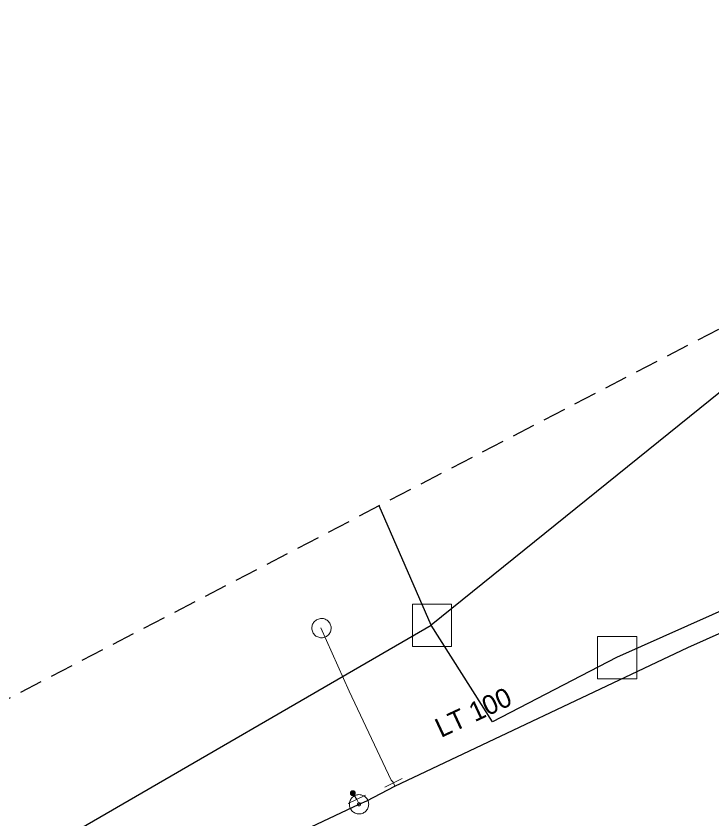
# Model space of a CAD drawing. Extents: x -688693 to -688474, y -974081 to -973994.
# Drawn here: x -688620.11 to -688584.02, y -974035.86 to -973994.23 of the extents above; entities that cross this region are included whole.
import ezdxf

# ---------------------------------------------------------------- set-up
doc = ezdxf.new("R2010")
doc.units = 0
doc.header["$LTSCALE"] = 0.4
doc.linetypes.add('MEDIUM_DASHED', pattern=[4.5, 3, -1.5])
for name, color, linetype, lineweight in [('1', 7, 'MEDIUM_DASHED', 25), ('13', 7, 'Continuous', 13), ('14', 7, 'Continuous', 25), ('17', 7, 'Continuous', 25), ('22', 7, 'Continuous', 13), ('23', 7, 'Continuous', 13), ('34', 7, 'Continuous', 13), ('47', 7, 'Continuous', 13), ('9', 7, 'Continuous', 13)]:
    doc.layers.add(name, color=color, linetype=linetype, lineweight=lineweight)

msp = doc.modelspace()

# ---------------------------------------------------------------- linework, layer by layer
at = {"layer": '1'}
msp.add_lwpolyline([(-688692.931, -974052.713), (-688674.241, -974042.463), (-688662.987, -974051.708), (-688552.455, -973994.231), (-688543.813, -974004.28), (-688496.988, -974010.309), (-688488.949, -974009.103), (-688474.077, -974014.529), (-688476.69, -974033.621), (-688494.978, -974032.616), (-688541.804, -974022.367), (-688555.67, -974019.352), (-688572.552, -974027.19), (-688578.982, -974032.415), (-688581.193, -974043.669), (-688636.057, -974069.393), (-688655.149, -974067.182), (-688651.532, -974076.829), (-688666.202, -974081.049), (-688669.82, -974071.805), (-688685.294, -974080.647), (-688689.113, -974064.369), (-688682.883, -974060.751)], close=True, dxfattribs=at)
at = {"layer": '13'}
msp.add_lwpolyline([(-688600.541, -974033.989), (-688600.574, -974033.938), (-688600.659, -974033.84), (-688602.827, -974029.23), (-688604.3, -974025.953)], dxfattribs=at)
at = {"layer": '14'}
for p, q in [((-688577.23, -974008.592), (-688598.575, -974025.813)), ((-688598.575, -974025.813), (-688601.283, -974019.622)), ((-688658.556, -974060.52), (-688598.575, -974025.813))]:
    msp.add_line(p, q, dxfattribs=at)
at = {"layer": '14', "lineweight": 13}
msp.add_line((-688600.46, -974034.151), (-688600.541, -974033.989), dxfattribs=at)
at = {"layer": '14'}
for points in [[(-688544.118, -974012.713), (-688553.402, -974013.335), (-688562.069, -974015.498), (-688588.977, -974027.483)], [(-688588.977, -974027.483), (-688595.407, -974030.817), (-688598.575, -974025.813)]]:
    msp.add_lwpolyline(points, dxfattribs=at)
at = {"layer": '14', "lineweight": 13}
msp.add_lwpolyline([(-688602.322, -974035.098), (-688602.44, -974034.846), (-688602.642, -974034.52)], dxfattribs=at)
at = {"layer": '17'}
for points in [[(-688602.322, -974035.098), (-688601.921, -974034.916), (-688600.46, -974034.151), (-688585.27, -974026.962), (-688583.34, -974026.112), (-688583.05, -974025.995)], [(-688652.752, -974058.945), (-688651.228, -974058.19), (-688641.695, -974053.653), (-688634.831, -974050.489), (-688629.499, -974047.91), (-688602.322, -974035.098)]]:
    msp.add_lwpolyline(points, dxfattribs=at)
at = {"layer": '22'}
for points in [[(-688599.554, -974024.723), (-688597.522, -974024.723), (-688597.522, -974026.916), (-688599.554, -974026.916)], [(-688589.956, -974026.393), (-688587.924, -974026.393), (-688587.924, -974028.586), (-688589.956, -974028.586)]]:
    msp.add_lwpolyline(points, close=True, dxfattribs=at)
at = {"layer": '23'}
for points in [[(-688603.779, -974026.06), (-688603.771, -974026.01), (-688603.77, -974025.957), (-688603.772, -974025.905), (-688603.782, -974025.853), (-688603.797, -974025.803), (-688603.816, -974025.755), (-688603.841, -974025.709), (-688603.869, -974025.665), (-688603.903, -974025.624), (-688603.941, -974025.588), (-688603.982, -974025.555), (-688604.025, -974025.528), (-688604.073, -974025.505), (-688604.122, -974025.486), (-688604.172, -974025.474), (-688604.225, -974025.466), (-688604.277, -974025.464), (-688604.329, -974025.468), (-688604.381, -974025.478), (-688604.431, -974025.492), (-688604.479, -974025.51), (-688604.526, -974025.535), (-688604.57, -974025.564), (-688604.609, -974025.598), (-688604.645, -974025.636), (-688604.678, -974025.676), (-688604.705, -974025.722), (-688604.728, -974025.768), (-688604.746, -974025.817), (-688604.759, -974025.868), (-688604.767, -974025.919), (-688604.769, -974025.972), (-688604.765, -974026.025), (-688604.757, -974026.076), (-688604.742, -974026.125), (-688604.723, -974026.174), (-688604.698, -974026.222), (-688604.67, -974026.264), (-688604.635, -974026.305)], [(-688604.479, -974025.51), (-688604.526, -974025.535), (-688604.57, -974025.564), (-688604.609, -974025.598), (-688604.645, -974025.636), (-688604.678, -974025.676), (-688604.705, -974025.722), (-688604.728, -974025.768), (-688604.746, -974025.817), (-688604.759, -974025.868), (-688604.767, -974025.919), (-688604.769, -974025.972), (-688604.765, -974026.025), (-688604.757, -974026.076), (-688604.742, -974026.125), (-688604.723, -974026.174), (-688604.698, -974026.222), (-688604.67, -974026.264), (-688604.635, -974026.305), (-688604.599, -974026.341), (-688604.558, -974026.374), (-688604.512, -974026.401), (-688604.465, -974026.424), (-688604.415, -974026.442), (-688604.365, -974026.456), (-688604.314, -974026.462), (-688604.261, -974026.464), (-688604.21, -974026.46), (-688604.158, -974026.451), (-688604.108, -974026.436), (-688604.059, -974026.418), (-688604.013, -974026.394), (-688603.969, -974026.364), (-688603.928, -974026.33), (-688603.892, -974026.293), (-688603.862, -974026.252), (-688603.833, -974026.208), (-688603.809, -974026.161), (-688603.791, -974026.111), (-688603.779, -974026.06)], [(-688604.635, -974026.305), (-688604.599, -974026.341), (-688604.558, -974026.374), (-688604.512, -974026.401), (-688604.465, -974026.424), (-688604.415, -974026.442), (-688604.365, -974026.456), (-688604.314, -974026.462), (-688604.261, -974026.464), (-688604.21, -974026.46), (-688604.158, -974026.451), (-688604.108, -974026.436), (-688604.059, -974026.418), (-688604.013, -974026.394), (-688603.969, -974026.364), (-688603.928, -974026.33), (-688603.892, -974026.293), (-688603.862, -974026.252), (-688603.833, -974026.208), (-688603.809, -974026.161), (-688603.791, -974026.111), (-688603.779, -974026.06), (-688603.771, -974026.01), (-688603.77, -974025.957), (-688603.772, -974025.905), (-688603.782, -974025.853), (-688603.797, -974025.803), (-688603.816, -974025.755), (-688603.841, -974025.709), (-688603.869, -974025.665), (-688603.903, -974025.624), (-688603.941, -974025.588), (-688603.982, -974025.555), (-688604.025, -974025.528), (-688604.073, -974025.505), (-688604.122, -974025.486), (-688604.172, -974025.474), (-688604.225, -974025.466), (-688604.277, -974025.464), (-688604.329, -974025.468)], [(-688604.329, -974025.468), (-688604.381, -974025.478), (-688604.431, -974025.492), (-688604.479, -974025.51)]]:
    msp.add_lwpolyline(points, dxfattribs=at)
at = {"layer": '34'}
for p, q in [((-688600.989, -974034.209), (-688600.091, -974033.769)), ((-688602.891, -974035.061), (-688601.988, -974034.631))]:
    msp.add_line(p, q, dxfattribs=at)
at = {"layer": '47'}
for points in [[(-688601.866, -974034.891), (-688601.89, -974034.845), (-688601.919, -974034.801), (-688601.952, -974034.761), (-688601.989, -974034.724), (-688602.03, -974034.691), (-688602.075, -974034.663), (-688602.121, -974034.64), (-688602.17, -974034.622), (-688602.22, -974034.608), (-688602.272, -974034.6), (-688602.325, -974034.597), (-688602.377, -974034.601), (-688602.428, -974034.609), (-688602.479, -974034.623), (-688602.528, -974034.642), (-688602.574, -974034.666), (-688602.618, -974034.695), (-688602.659, -974034.729), (-688602.695, -974034.765), (-688602.728, -974034.806), (-688602.756, -974034.851), (-688602.78, -974034.898), (-688602.798, -974034.947), (-688602.812, -974034.997), (-688602.819, -974035.048), (-688602.822, -974035.101), (-688602.819, -974035.154), (-688602.81, -974035.204), (-688602.796, -974035.255), (-688602.777, -974035.304), (-688602.753, -974035.35), (-688602.724, -974035.394), (-688602.691, -974035.435), (-688602.654, -974035.471), (-688602.613, -974035.504), (-688602.569, -974035.532), (-688602.522, -974035.556), (-688602.473, -974035.575), (-688602.422, -974035.588), (-688602.371, -974035.595), (-688602.318, -974035.598), (-688602.266, -974035.595), (-688602.215, -974035.586), (-688602.164, -974035.572), (-688602.115, -974035.553), (-688602.069, -974035.529), (-688602.025, -974035.5), (-688601.985, -974035.468), (-688601.948, -974035.43), (-688601.915, -974035.389), (-688601.887, -974035.345), (-688601.864, -974035.299), (-688601.845, -974035.25), (-688601.832, -974035.199), (-688601.824, -974035.147), (-688601.821, -974035.094), (-688601.825, -974035.043), (-688601.833, -974034.991), (-688601.847, -974034.94)], [(-688602.247, -974035.064), (-688602.251, -974035.055), (-688602.256, -974035.049), (-688602.261, -974035.043), (-688602.267, -974035.037), (-688602.274, -974035.031), (-688602.281, -974035.027), (-688602.289, -974035.022), (-688602.297, -974035.019), (-688602.305, -974035.018), (-688602.313, -974035.016), (-688602.322, -974035.016), (-688602.331, -974035.016), (-688602.339, -974035.018), (-688602.347, -974035.019), (-688602.355, -974035.023), (-688602.364, -974035.027), (-688602.37, -974035.032), (-688602.376, -974035.037), (-688602.382, -974035.043), (-688602.388, -974035.05), (-688602.392, -974035.057), (-688602.397, -974035.065), (-688602.4, -974035.073), (-688602.402, -974035.081), (-688602.403, -974035.089), (-688602.403, -974035.098), (-688602.403, -974035.107), (-688602.401, -974035.115), (-688602.4, -974035.123), (-688602.396, -974035.131), (-688602.392, -974035.14), (-688602.387, -974035.146), (-688602.382, -974035.152), (-688602.376, -974035.158), (-688602.369, -974035.164), (-688602.363, -974035.169), (-688602.354, -974035.173), (-688602.346, -974035.176), (-688602.338, -974035.178), (-688602.33, -974035.179), (-688602.321, -974035.179), (-688602.312, -974035.179), (-688602.304, -974035.177), (-688602.296, -974035.176), (-688602.288, -974035.172), (-688602.279, -974035.168), (-688602.273, -974035.163), (-688602.267, -974035.158), (-688602.261, -974035.152), (-688602.255, -974035.145), (-688602.25, -974035.139), (-688602.246, -974035.13), (-688602.243, -974035.122), (-688602.242, -974035.114), (-688602.24, -974035.106), (-688602.24, -974035.097), (-688602.24, -974035.088), (-688602.242, -974035.08), (-688602.243, -974035.072)]]:
    msp.add_lwpolyline(points, close=True, dxfattribs=at)
at = {"layer": '9'}
for points in [[(-688602.768, -974034.52), (-688602.768, -974034.533), (-688602.766, -974034.546), (-688602.763, -974034.559), (-688602.758, -974034.571), (-688602.752, -974034.583), (-688602.745, -974034.594), (-688602.737, -974034.604), (-688602.727, -974034.614), (-688602.717, -974034.622), (-688602.706, -974034.629), (-688602.694, -974034.635), (-688602.682, -974034.64), (-688602.669, -974034.643), (-688602.656, -974034.645), (-688602.643, -974034.647), (-688602.63, -974034.646), (-688602.617, -974034.644), (-688602.604, -974034.641), (-688602.592, -974034.636), (-688602.58, -974034.63), (-688602.569, -974034.623), (-688602.559, -974034.615), (-688602.549, -974034.605), (-688602.541, -974034.595), (-688602.534, -974034.584), (-688602.528, -974034.572), (-688602.523, -974034.56), (-688602.52, -974034.547), (-688602.518, -974034.534), (-688602.516, -974034.521), (-688602.517, -974034.508), (-688602.519, -974034.495), (-688602.522, -974034.482), (-688602.527, -974034.47), (-688602.532, -974034.458), (-688602.54, -974034.447), (-688602.548, -974034.437), (-688602.558, -974034.427), (-688602.568, -974034.419), (-688602.579, -974034.412), (-688602.591, -974034.406), (-688602.603, -974034.401), (-688602.616, -974034.398), (-688602.629, -974034.396), (-688602.642, -974034.395), (-688602.655, -974034.395), (-688602.668, -974034.397), (-688602.681, -974034.4), (-688602.693, -974034.405), (-688602.705, -974034.411), (-688602.716, -974034.418), (-688602.726, -974034.426), (-688602.736, -974034.436), (-688602.744, -974034.446), (-688602.751, -974034.457), (-688602.757, -974034.469), (-688602.762, -974034.481), (-688602.765, -974034.494), (-688602.767, -974034.507)], [(-688602.748, -974034.52), (-688602.749, -974034.531), (-688602.747, -974034.542), (-688602.744, -974034.553), (-688602.74, -974034.563), (-688602.735, -974034.573), (-688602.729, -974034.582), (-688602.722, -974034.591), (-688602.714, -974034.599), (-688602.705, -974034.606), (-688602.696, -974034.612), (-688602.686, -974034.617), (-688602.676, -974034.621), (-688602.665, -974034.624), (-688602.654, -974034.627), (-688602.643, -974034.627), (-688602.632, -974034.627), (-688602.621, -974034.625), (-688602.61, -974034.622), (-688602.6, -974034.618), (-688602.59, -974034.613), (-688602.581, -974034.607), (-688602.572, -974034.6), (-688602.564, -974034.592), (-688602.557, -974034.583), (-688602.551, -974034.574), (-688602.546, -974034.564), (-688602.542, -974034.554), (-688602.539, -974034.543), (-688602.537, -974034.532), (-688602.536, -974034.521), (-688602.536, -974034.51), (-688602.538, -974034.499), (-688602.541, -974034.488), (-688602.545, -974034.478), (-688602.55, -974034.468), (-688602.556, -974034.459), (-688602.563, -974034.45), (-688602.571, -974034.442), (-688602.58, -974034.435), (-688602.589, -974034.429), (-688602.599, -974034.424), (-688602.608, -974034.42), (-688602.62, -974034.417), (-688602.63, -974034.415), (-688602.642, -974034.415), (-688602.653, -974034.414), (-688602.664, -974034.416), (-688602.675, -974034.419), (-688602.684, -974034.423), (-688602.695, -974034.428), (-688602.704, -974034.434), (-688602.713, -974034.441), (-688602.721, -974034.449), (-688602.728, -974034.458), (-688602.733, -974034.467), (-688602.739, -974034.477), (-688602.743, -974034.487), (-688602.746, -974034.498), (-688602.748, -974034.509)], [(-688602.729, -974034.52), (-688602.729, -974034.529), (-688602.728, -974034.538), (-688602.725, -974034.547), (-688602.722, -974034.555), (-688602.718, -974034.563), (-688602.713, -974034.571), (-688602.706, -974034.578), (-688602.701, -974034.584), (-688602.694, -974034.59), (-688602.686, -974034.595), (-688602.678, -974034.599), (-688602.67, -974034.602), (-688602.661, -974034.605), (-688602.652, -974034.606), (-688602.643, -974034.608), (-688602.634, -974034.607), (-688602.625, -974034.606), (-688602.616, -974034.603), (-688602.608, -974034.6), (-688602.6, -974034.596), (-688602.592, -974034.591), (-688602.585, -974034.585), (-688602.579, -974034.579), (-688602.573, -974034.572), (-688602.568, -974034.564), (-688602.564, -974034.556), (-688602.561, -974034.548), (-688602.558, -974034.539), (-688602.557, -974034.53), (-688602.554, -974034.521), (-688602.556, -974034.512), (-688602.557, -974034.503), (-688602.559, -974034.494), (-688602.563, -974034.486), (-688602.567, -974034.478), (-688602.572, -974034.47), (-688602.578, -974034.463), (-688602.584, -974034.457), (-688602.591, -974034.451), (-688602.599, -974034.446), (-688602.607, -974034.442), (-688602.615, -974034.439), (-688602.624, -974034.436), (-688602.633, -974034.435), (-688602.642, -974034.434), (-688602.651, -974034.434), (-688602.66, -974034.435), (-688602.669, -974034.438), (-688602.677, -974034.441), (-688602.684, -974034.445), (-688602.693, -974034.45), (-688602.7, -974034.456), (-688602.706, -974034.462), (-688602.712, -974034.469), (-688602.717, -974034.477), (-688602.721, -974034.485), (-688602.724, -974034.493), (-688602.727, -974034.502), (-688602.728, -974034.511)], [(-688602.709, -974034.52), (-688602.709, -974034.527), (-688602.708, -974034.534), (-688602.706, -974034.541), (-688602.704, -974034.547), (-688602.701, -974034.553), (-688602.697, -974034.559), (-688602.693, -974034.565), (-688602.688, -974034.57), (-688602.682, -974034.574), (-688602.676, -974034.578), (-688602.67, -974034.581), (-688602.664, -974034.584), (-688602.657, -974034.585), (-688602.65, -974034.588), (-688602.643, -974034.588), (-688602.636, -974034.588), (-688602.629, -974034.586), (-688602.622, -974034.585), (-688602.616, -974034.582), (-688602.608, -974034.579), (-688602.604, -974034.575), (-688602.598, -974034.571), (-688602.593, -974034.566), (-688602.589, -974034.56), (-688602.585, -974034.554), (-688602.581, -974034.548), (-688602.579, -974034.542), (-688602.577, -974034.535), (-688602.576, -974034.528), (-688602.575, -974034.521), (-688602.575, -974034.514), (-688602.576, -974034.507), (-688602.578, -974034.5), (-688602.581, -974034.494), (-688602.584, -974034.487), (-688602.588, -974034.482), (-688602.592, -974034.476), (-688602.597, -974034.471), (-688602.603, -974034.467), (-688602.608, -974034.463), (-688602.615, -974034.46), (-688602.621, -974034.457), (-688602.628, -974034.455), (-688602.635, -974034.454), (-688602.642, -974034.454), (-688602.649, -974034.454), (-688602.656, -974034.454), (-688602.663, -974034.456), (-688602.669, -974034.459), (-688602.675, -974034.462), (-688602.681, -974034.466), (-688602.687, -974034.47), (-688602.692, -974034.475), (-688602.696, -974034.481), (-688602.7, -974034.486), (-688602.703, -974034.493), (-688602.706, -974034.499), (-688602.706, -974034.506), (-688602.709, -974034.513)], [(-688602.689, -974034.52), (-688602.689, -974034.525), (-688602.689, -974034.53), (-688602.688, -974034.535), (-688602.686, -974034.539), (-688602.684, -974034.544), (-688602.681, -974034.548), (-688602.678, -974034.551), (-688602.674, -974034.555), (-688602.671, -974034.558), (-688602.667, -974034.561), (-688602.662, -974034.563), (-688602.657, -974034.565), (-688602.653, -974034.566), (-688602.648, -974034.568), (-688602.643, -974034.568), (-688602.638, -974034.568), (-688602.633, -974034.567), (-688602.628, -974034.566), (-688602.624, -974034.564), (-688602.619, -974034.562), (-688602.615, -974034.559), (-688602.611, -974034.556), (-688602.608, -974034.552), (-688602.605, -974034.549), (-688602.602, -974034.545), (-688602.6, -974034.54), (-688602.598, -974034.536), (-688602.597, -974034.531), (-688602.596, -974034.526), (-688602.595, -974034.521), (-688602.595, -974034.516), (-688602.596, -974034.511), (-688602.597, -974034.506), (-688602.599, -974034.502), (-688602.601, -974034.497), (-688602.604, -974034.493), (-688602.607, -974034.489), (-688602.61, -974034.486), (-688602.614, -974034.483), (-688602.618, -974034.48), (-688602.623, -974034.478), (-688602.627, -974034.476), (-688602.632, -974034.475), (-688602.637, -974034.474), (-688602.642, -974034.474), (-688602.647, -974034.474), (-688602.652, -974034.475), (-688602.657, -974034.475), (-688602.661, -974034.477), (-688602.666, -974034.479), (-688602.67, -974034.482), (-688602.673, -974034.485), (-688602.677, -974034.488), (-688602.679, -974034.492), (-688602.683, -974034.496), (-688602.684, -974034.501), (-688602.687, -974034.505), (-688602.688, -974034.51), (-688602.689, -974034.515)], [(-688602.669, -974034.52), (-688602.669, -974034.523), (-688602.67, -974034.526), (-688602.669, -974034.528), (-688602.668, -974034.531), (-688602.667, -974034.534), (-688602.665, -974034.536), (-688602.663, -974034.538), (-688602.661, -974034.54), (-688602.659, -974034.542), (-688602.657, -974034.544), (-688602.654, -974034.546), (-688602.651, -974034.547), (-688602.649, -974034.547), (-688602.646, -974034.548), (-688602.643, -974034.548), (-688602.64, -974034.548), (-688602.637, -974034.548), (-688602.634, -974034.547), (-688602.632, -974034.546), (-688602.629, -974034.545), (-688602.627, -974034.543), (-688602.624, -974034.541), (-688602.622, -974034.539), (-688602.621, -974034.537), (-688602.619, -974034.535), (-688602.618, -974034.532), (-688602.616, -974034.529), (-688602.616, -974034.527), (-688602.615, -974034.524), (-688602.614, -974034.521), (-688602.615, -974034.518), (-688602.615, -974034.515), (-688602.616, -974034.512), (-688602.617, -974034.51), (-688602.618, -974034.507), (-688602.62, -974034.505), (-688602.621, -974034.502), (-688602.623, -974034.5), (-688602.626, -974034.499), (-688602.628, -974034.497), (-688602.63, -974034.496), (-688602.633, -974034.495), (-688602.636, -974034.494), (-688602.639, -974034.494), (-688602.642, -974034.493), (-688602.645, -974034.494), (-688602.648, -974034.493), (-688602.65, -974034.495), (-688602.653, -974034.495), (-688602.656, -974034.496), (-688602.657, -974034.498), (-688602.66, -974034.499), (-688602.662, -974034.501), (-688602.664, -974034.504), (-688602.666, -974034.506), (-688602.667, -974034.509), (-688602.668, -974034.511), (-688602.669, -974034.514), (-688602.669, -974034.517)], [(-688602.65, -974034.52), (-688602.65, -974034.522), (-688602.65, -974034.522), (-688602.649, -974034.522), (-688602.649, -974034.524), (-688602.65, -974034.525), (-688602.648, -974034.525), (-688602.648, -974034.525), (-688602.648, -974034.527), (-688602.648, -974034.527), (-688602.647, -974034.528), (-688602.645, -974034.528), (-688602.645, -974034.528), (-688602.645, -974034.529), (-688602.643, -974034.529), (-688602.643, -974034.529), (-688602.642, -974034.529), (-688602.641, -974034.529), (-688602.641, -974034.528), (-688602.64, -974034.528), (-688602.638, -974034.528), (-688602.638, -974034.527), (-688602.638, -974034.527), (-688602.637, -974034.526), (-688602.637, -974034.526), (-688602.635, -974034.525), (-688602.635, -974034.524), (-688602.634, -974034.523), (-688602.634, -974034.523), (-688602.634, -974034.522), (-688602.634, -974034.521), (-688602.634, -974034.52), (-688602.634, -974034.519), (-688602.634, -974034.519), (-688602.635, -974034.518), (-688602.635, -974034.517), (-688602.636, -974034.516), (-688602.636, -974034.516), (-688602.637, -974034.515), (-688602.637, -974034.515), (-688602.638, -974034.514), (-688602.639, -974034.514), (-688602.64, -974034.513), (-688602.64, -974034.513), (-688602.641, -974034.513), (-688602.642, -974034.513), (-688602.643, -974034.513), (-688602.644, -974034.513), (-688602.644, -974034.513), (-688602.645, -974034.514), (-688602.646, -974034.513), (-688602.647, -974034.515), (-688602.647, -974034.515), (-688602.648, -974034.515), (-688602.648, -974034.515), (-688602.649, -974034.517), (-688602.649, -974034.518), (-688602.649, -974034.519), (-688602.65, -974034.519), (-688602.65, -974034.52)]]:
    msp.add_lwpolyline(points, close=True, dxfattribs=at)

# ---------------------------------------------------------------- texts
at = {"layer": '1'}
msp.add_text('LT 100', height=1, rotation=25, dxfattribs=at).set_placement((-688598.073, -974031.663))

doc.saveas('drawing.dxf')
